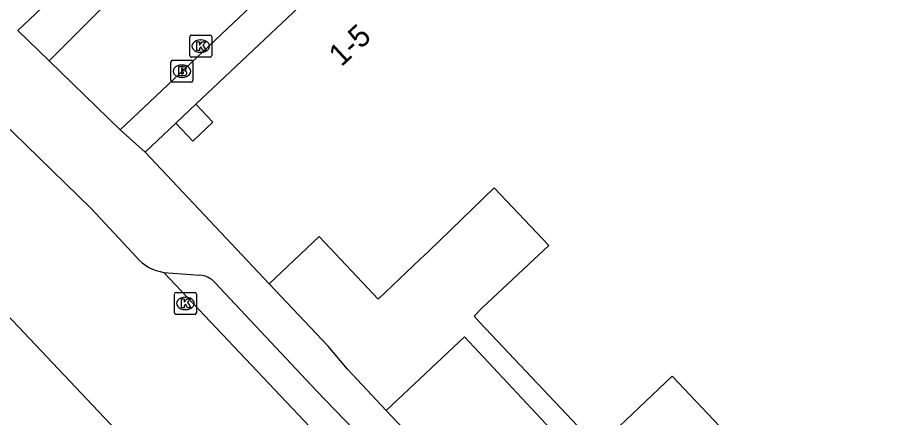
# Model space of a CAD drawing. Extents: x 162532 to 163264, y 381233 to 382042.
# Drawn here: x 163096.93 to 163136.79, y 381503.3 to 381521.43 of the extents above; entities that cross this region are included whole.
import ezdxf

# ---------------------------------------------------------------- set-up
doc = ezdxf.new("R2010")
doc.units = 0
for name, color, linetype in [('IMGEO_Brandkraan', 7, 'Continuous'), ('IMGEO_Haag', 7, 'Continuous'), ('IMGEO_Kolk', 7, 'Continuous'), ('IMGEO_Muur', 7, 'Continuous'), ('IMGEO_Pand', 7, 'Continuous'), ('IMGEO_Pand_nummerreeks', 7, 'Continuous'), ('IMGEO_Pand_overbouw', 7, 'Continuous'), ('IMGEO_Rijbaan_lokaal_open', 7, 'Continuous'), ('IMGEO_Voetpad_open', 7, 'Continuous')]:
    doc.layers.add(name, color=color, linetype=linetype)

msp = doc.modelspace()

# ---------------------------------------------------------------- linework, layer by layer
at = {"layer": 'IMGEO_Brandkraan'}
for p, q in [((163103.882, 381518.57), (163103.882, 381519.422)), ((163103.957, 381519.496), (163104.809, 381519.496)), ((163104.37, 381519.276), (163104.395, 381519.276)), ((163104.883, 381519.422), (163104.883, 381518.57)), ((163104.809, 381518.496), (163103.957, 381518.496)), ((163104.393, 381518.716), (163104.368, 381518.716))]:
    msp.add_line(p, q, dxfattribs=at)
for points in [[(163103.882, 381518.57), (163103.882, 381519.422)], [(163103.957, 381519.496), (163104.809, 381519.496)], [(163104.883, 381519.422), (163104.883, 381518.57)], [(163104.23, 381519.196), (163104.23, 381518.796), (163104.443, 381518.796)], [(163104.461, 381519.196), (163104.23, 381519.196)], [(163104.409, 381519.115), (163104.355, 381519.115), (163104.355, 381519.039)], [(163104.355, 381519.039), (163104.408, 381519.039)], [(163104.417, 381518.963), (163104.355, 381518.963), (163104.355, 381518.882)], [(163104.355, 381518.882), (163104.417, 381518.882)], [(163104.809, 381518.496), (163103.957, 381518.496)]]:
    msp.add_lwpolyline(points, dxfattribs=at)
for centre, radius, start, end in [((163103.959, 381519.42), 0.0765, 91.552, 178.448), ((163103.959, 381519.42), 0.0765, 91.552, 178.448), ((163104.807, 381519.42), 0.0765, 1.552, 88.448), ((163104.807, 381519.42), 0.0765, 1.552, 88.448), ((163104.41, 381519.077), 0.0379, 267.8285, 90.9355), ((163104.418, 381518.922), 0.0404, 269.8759, 90.5077), ((163104.449, 381519.047), 0.251, 268.6676, 293.5347), ((163104.465, 381519.051), 0.145, 59.4692, 91.5367), ((163104.49, 381519.098), 0.0922, 285.5137, 58.1501), ((163104.495, 381518.906), 0.105, 301.3115, 78.989), ((163103.959, 381518.572), 0.0765, 181.552, 268.448), ((163103.959, 381518.572), 0.0765, 181.552, 268.448), ((163104.807, 381518.572), 0.0765, 271.552, 358.448), ((163104.807, 381518.572), 0.0765, 271.552, 358.448)]:
    msp.add_arc(centre, radius, start, end, dxfattribs=at)
for centre, major_axis, ratio, start_param, end_param in [((163104.369, 381518.996), (-0.387, 0.002), 0.722429, 4.712389, 7.853982), ((163104.394, 381518.996), (-0.39, 0.002), 0.717154, 1.570796, 4.712389)]:
    msp.add_ellipse(centre, major_axis=major_axis, ratio=ratio, start_param=start_param, end_param=end_param, dxfattribs=at)
at = {"layer": 'IMGEO_Haag'}
msp.add_lwpolyline([(163113.645, 381503.623), (163117.199, 381506.949), (163122.4, 381501.391), (163118.88, 381498.086)], dxfattribs=at)
at = {"layer": 'IMGEO_Kolk'}
for p, q in [((163104.733, 381519.708), (163104.733, 381520.56)), ((163104.808, 381520.634), (163105.66, 381520.634)), ((163105.221, 381520.414), (163105.246, 381520.414)), ((163105.734, 381520.56), (163105.734, 381519.708)), ((163105.66, 381519.634), (163104.808, 381519.634)), ((163105.244, 381519.854), (163105.219, 381519.854)), ((163104.04, 381508.046), (163104.04, 381508.898)), ((163104.115, 381508.972), (163104.967, 381508.972)), ((163105.041, 381508.898), (163105.041, 381508.046)), ((163104.528, 381508.752), (163104.553, 381508.752)), ((163104.551, 381508.192), (163104.526, 381508.192)), ((163104.967, 381507.972), (163104.115, 381507.972))]:
    msp.add_line(p, q, dxfattribs=at)
for points in [[(163104.733, 381519.708), (163104.733, 381520.56)], [(163104.808, 381520.634), (163105.66, 381520.634)], [(163105.734, 381520.56), (163105.734, 381519.708)], [(163105.054, 381520.334), (163105.177, 381520.334), (163105.177, 381520.183), (163105.307, 381520.334), (163105.471, 381520.334), (163105.325, 381520.183), (163105.478, 381519.934), (163105.326, 381519.934), (163105.241, 381520.098), (163105.177, 381520.031), (163105.177, 381519.934), (163105.054, 381519.934), (163105.054, 381520.334)], [(163105.66, 381519.634), (163104.808, 381519.634)], [(163104.04, 381508.046), (163104.04, 381508.898)], [(163104.115, 381508.972), (163104.967, 381508.972)], [(163105.041, 381508.898), (163105.041, 381508.046)], [(163104.361, 381508.672), (163104.484, 381508.672), (163104.484, 381508.521), (163104.614, 381508.672), (163104.778, 381508.672), (163104.632, 381508.521), (163104.785, 381508.272), (163104.633, 381508.272), (163104.548, 381508.436), (163104.484, 381508.369), (163104.484, 381508.272), (163104.361, 381508.272), (163104.361, 381508.672)], [(163104.967, 381507.972), (163104.115, 381507.972)]]:
    msp.add_lwpolyline(points, dxfattribs=at)
for centre, start, end in [((163104.81, 381520.558), 91.552, 178.448), ((163104.81, 381520.558), 91.552, 178.448), ((163105.658, 381520.558), 1.552, 88.448), ((163105.658, 381520.558), 1.552, 88.448), ((163104.81, 381519.71), 181.552, 268.448), ((163104.81, 381519.71), 181.552, 268.448), ((163105.658, 381519.71), 271.552, 358.448), ((163105.658, 381519.71), 271.552, 358.448), ((163104.117, 381508.896), 91.552, 178.448), ((163104.117, 381508.896), 91.552, 178.448), ((163104.965, 381508.896), 1.552, 88.448), ((163104.965, 381508.896), 1.552, 88.448), ((163104.117, 381508.048), 181.552, 268.448), ((163104.117, 381508.048), 181.552, 268.448), ((163104.965, 381508.048), 271.552, 358.448), ((163104.965, 381508.048), 271.552, 358.448)]:
    msp.add_arc(centre, 0.0765, start, end, dxfattribs=at)
for centre, major_axis, ratio, start_param, end_param in [((163105.22, 381520.134), (-0.387, 0.002), 0.722429, 4.712389, 7.853982), ((163105.245, 381520.134), (-0.39, 0.002), 0.717154, 1.570796, 4.712389), ((163104.527, 381508.472), (-0.387, 0.002), 0.722429, 4.712389, 7.853982), ((163104.552, 381508.472), (-0.39, 0.002), 0.717154, 1.570796, 4.712389)]:
    msp.add_ellipse(centre, major_axis=major_axis, ratio=ratio, start_param=start_param, end_param=end_param, dxfattribs=at)
at = {"layer": 'IMGEO_Muur'}
msp.add_lwpolyline([(163111.016, 381506.526), (163108.343, 381509.358)], dxfattribs=at)
at = {"layer": 'IMGEO_Pand'}
for points in [[(163110.743, 381522.913), (163105.019, 381517.497)], [(163105.019, 381517.497), (163105.789, 381516.684), (163104.875, 381515.829), (163104.105, 381516.642)], [(163104.105, 381516.642), (163102.711, 381515.323)], [(163108.343, 381509.358), (163102.711, 381515.323)], [(163123.134, 381502.08), (163117.902, 381507.607), (163117.634, 381507.89), (163118.007, 381508.267), (163121.025, 381511.101), (163118.543, 381513.705), (163115.579, 381510.842), (163115.194, 381510.473), (163113.282, 381508.663), (163110.605, 381511.507), (163108.343, 381509.358)], [(163131.741, 381499.757), (163126.624, 381505.172), (163123.626, 381502.334)]]:
    msp.add_lwpolyline(points, dxfattribs=at)
at = {"layer": 'IMGEO_Pand_overbouw'}
msp.add_lwpolyline([(163104.105, 381516.642), (163104.875, 381515.829), (163105.789, 381516.684), (163105.019, 381517.497)], close=True, dxfattribs=at)
at = {"layer": 'IMGEO_Rijbaan_lokaal_open'}
for points in [[(163127.716, 381541.024), (163101.581, 381516.34)], [(163080.697, 381532.76), (163089.836, 381522.91), (163091.451, 381521.34), (163094.355, 381518.519), (163100.274, 381512.762), (163102.323, 381510.571)], [(163111.655, 381532.733), (163098.36, 381519.475)], [(163101.581, 381516.34), (163098.36, 381519.475)], [(163135.737, 381466.525), (163121.57, 381481.459), (163105.324, 381498.575), (163103.975, 381500), (163089.162, 381515.65), (163086.997, 381517.925), (163086.854, 381518.075)], [(163103.568, 381509.88), (163153.839, 381456.764)]]:
    msp.add_lwpolyline(points, dxfattribs=at)
msp.add_arc((163103.821, 381511.803), 1.94, 219.4333, 262.5044, dxfattribs=at)
at = {"layer": 'IMGEO_Voetpad_open'}
for points in [[(163098.36, 381519.475), (163096.934, 381520.847), (163110.646, 381533.802), (163111.655, 381532.733)], [(163104.105, 381516.642), (163105.019, 381517.497)], [(163102.711, 381515.323), (163101.581, 381516.34)], [(163103.568, 381509.88), (163105.199, 381509.757)], [(163105.878, 381509.418), (163110.49, 381504.514), (163112.58, 381502.341), (163117.116, 381497.542), (163123.28, 381490.987), (163128.284, 381485.708), (163133.961, 381479.729), (163138.664, 381474.76), (163141.227, 381472.04), (163145.704, 381467.321), (163149.855, 381462.952), (163153.441, 381459.174)], [(163113.645, 381503.623), (163111.89, 381505.496), (163111.016, 381506.526), (163108.343, 381509.358)], [(163118.88, 381498.086), (163113.645, 381503.623)]]:
    msp.add_lwpolyline(points, dxfattribs=at)
msp.add_arc((163105.101, 381508.71), 1.051, 42.3068, 84.6306, dxfattribs=at)

# ---------------------------------------------------------------- texts
at = {"layer": 'IMGEO_Pand_nummerreeks'}
msp.add_text('1-5', height=1, rotation=42.7094, dxfattribs=at).set_placement((163111.614, 381519.171))

doc.saveas('drawing.dxf')
